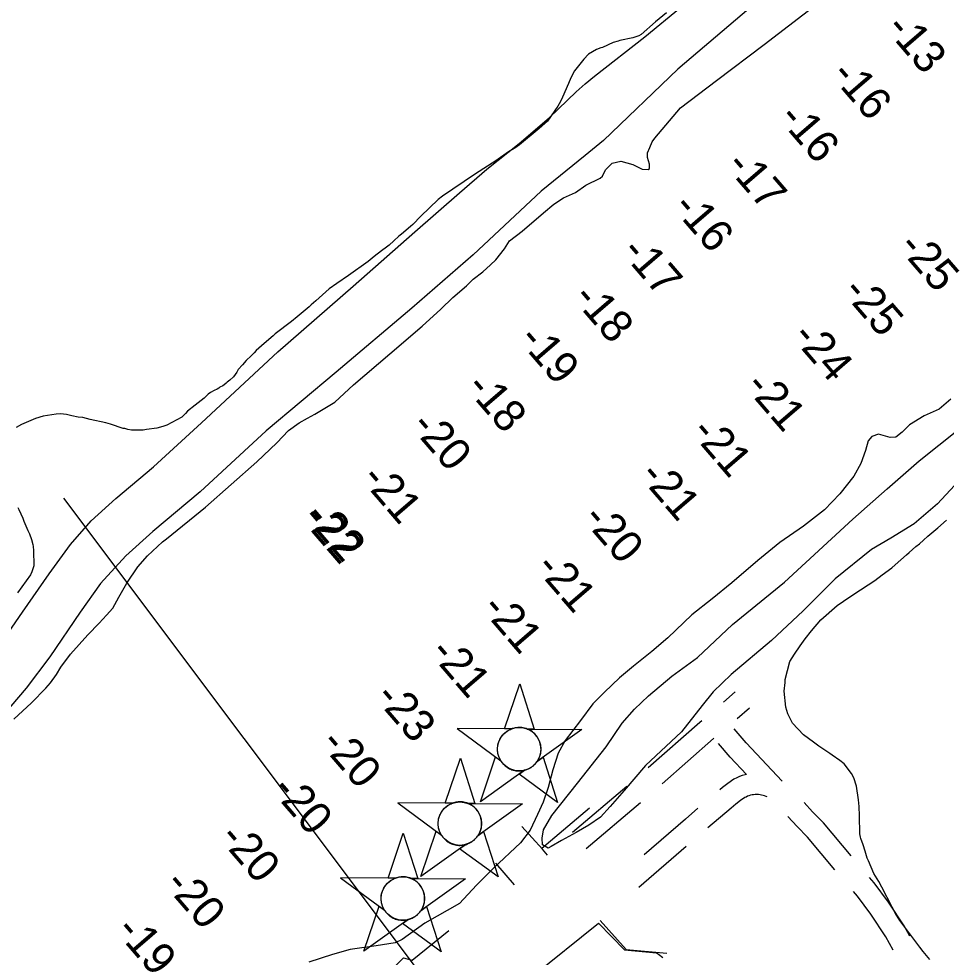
# Model space of a CAD drawing. Extents: x 3704301 to 3742427, y 506229 to 532009.
# Drawn here: x 3709544 to 3710847, y 515118 to 516437 of the extents above; entities that cross this region are included whole.
import ezdxf

# ---------------------------------------------------------------- set-up
doc = ezdxf.new("R2010")
doc.units = 0
for name, color, linetype in [('V-CHAN-NAID', 7, 'Continuous'), ('V-FLOD-BASE', 7, 'Continuous'), ('V-LEVE-TOET', 7, 'Continuous'), ('V-ROAD-CNTR', 7, 'Continuous'), ('V-RRAP-FSHR', 7, 'Continuous'), ('V-SITE-VEGE', 7, 'Continuous'), ('V-TOPO-SHOR', 7, 'Continuous'), ('V-TOPO-SPOT', 7, 'Continuous'), ('V-UTIL-LINE', 7, 'Continuous')]:
    doc.layers.add(name, color=color, linetype=linetype)

msp = doc.modelspace()

# ---------------------------------------------------------------- linework, layer by layer
at = {"layer": 'V-CHAN-NAID'}
for points in [[(3710236.4, 515438.8), (3710226.8, 515438.9), (3710248, 515502.3), (3710268.2, 515438.6), (3710258.6, 515438.6), (3710257, 515439.2), (3710254.9, 515439.8), (3710252.9, 515440.3), (3710250.9, 515440.6), (3710249.7, 515440.7), (3710248.2, 515440.8), (3710246.4, 515440.8), (3710245.1, 515440.7), (3710243.2, 515440.5), (3710241.8, 515440.3), (3710240, 515439.9), (3710238.5, 515439.5), (3710237.4, 515439.2)], [(3710236.4, 515438.8), (3710159.9, 515439.3), (3710221.5, 515393.9), (3710220.4, 515395.8), (3710219.6, 515397.5), (3710218.8, 515399.4), (3710218.1, 515401.5), (3710217.7, 515402.8), (3710217.3, 515404.4), (3710217.1, 515405.9), (3710216.9, 515407.5), (3710216.8, 515409.2), (3710216.8, 515410.8), (3710216.9, 515412.9), (3710217.1, 515414.5), (3710217.5, 515416.7), (3710217.9, 515418.6), (3710218.5, 515420.5), (3710219.2, 515422.2), (3710219.9, 515423.8), (3710220.7, 515425.3), (3710221.8, 515427.1), (3710222.8, 515428.5), (3710223.8, 515429.8), (3710224.8, 515430.9), (3710226.1, 515432.3), (3710227.2, 515433.2), (3710228.9, 515434.6), (3710230.1, 515435.5), (3710231.8, 515436.6), (3710233.5, 515437.5), (3710235, 515438.2)], [(3710258.6, 515438.6), (3710335.1, 515438.1), (3710272.9, 515393.6), (3710273.8, 515395.1), (3710274.8, 515396.9), (3710275.5, 515398.5), (3710276.2, 515400.5), (3710276.8, 515402.2), (3710277.2, 515403.9), (3710277.5, 515405.9), (3710277.7, 515407.5), (3710277.9, 515409.7), (3710277.8, 515411.7), (3710277.6, 515413.9), (3710277.4, 515415.7), (3710276.9, 515417.9), (3710276.2, 515420.1), (3710275.5, 515422.1), (3710274.8, 515423.5), (3710273.8, 515425.4), (3710272.8, 515427.1), (3710271.6, 515428.8), (3710270.3, 515430.4), (3710269, 515431.7), (3710267.4, 515433.3), (3710265.7, 515434.7), (3710264, 515435.9), (3710262.1, 515437), (3710260.6, 515437.8)], [(3710153, 515334.3), (3710143.4, 515334.3), (3710164.6, 515397.8), (3710184.8, 515334), (3710175.2, 515334.1), (3710173.6, 515334.7), (3710171.5, 515335.3), (3710169.5, 515335.7), (3710167.4, 515336.1), (3710166.3, 515336.2), (3710164.7, 515336.2), (3710163, 515336.2), (3710161.6, 515336.2), (3710159.7, 515336), (3710158.4, 515335.8), (3710156.6, 515335.4), (3710155.1, 515335), (3710154, 515334.6)], [(3710254.9, 515380.7), (3710192.7, 515336.1), (3710213.8, 515399.6), (3710221.5, 515393.9), (3710222.1, 515393), (3710223.5, 515391.1), (3710224.7, 515389.7), (3710226.2, 515388.2), (3710227.6, 515386.9), (3710229, 515385.8), (3710230.4, 515384.8), (3710232.1, 515383.8), (3710233.8, 515382.9), (3710235.6, 515382), (3710237.1, 515381.5), (3710238.7, 515381), (3710240.9, 515380.4), (3710242.5, 515380.1), (3710244.5, 515379.9), (3710246, 515379.7), (3710247.9, 515379.7), (3710249.6, 515379.8), (3710251.3, 515380), (3710253.2, 515380.3)], [(3710272.9, 515393.6), (3710280.7, 515399.2), (3710300.9, 515335.4), (3710247.1, 515375.1), (3710254.9, 515380.7), (3710256.5, 515381.1), (3710258.1, 515381.7), (3710260.3, 515382.6), (3710262, 515383.5), (3710263.9, 515384.6), (3710265.6, 515385.8), (3710267.2, 515387.1), (3710268.5, 515388.2), (3710269.9, 515389.7), (3710271.1, 515391.1), (3710272.2, 515392.5)], [(3710153, 515334.3), (3710076.5, 515334.8), (3710138.1, 515289.4), (3710137, 515291.3), (3710136.2, 515292.9), (3710135.3, 515294.9), (3710134.6, 515297), (3710134.3, 515298.3), (3710133.9, 515299.9), (3710133.7, 515301.3), (3710133.5, 515302.9), (3710133.4, 515304.7), (3710133.4, 515306.3), (3710133.5, 515308.3), (3710133.7, 515310), (3710134, 515312.2), (3710134.5, 515314.1), (3710135.1, 515316), (3710135.8, 515317.6), (3710136.5, 515319.2), (3710137.3, 515320.8), (3710138.4, 515322.5), (3710139.4, 515324), (3710140.4, 515325.2), (3710141.4, 515326.4), (3710142.7, 515327.7), (3710143.8, 515328.7), (3710145.5, 515330.1), (3710146.7, 515331), (3710148.4, 515332), (3710150.1, 515333), (3710151.6, 515333.7)], [(3710175.2, 515334.1), (3710251.7, 515333.6), (3710189.5, 515289), (3710190.4, 515290.5), (3710191.4, 515292.4), (3710192.1, 515294), (3710192.8, 515295.9), (3710193.4, 515297.7), (3710193.8, 515299.3), (3710194.1, 515301.3), (3710194.3, 515302.9), (3710194.4, 515305.1), (3710194.4, 515307.2), (3710194.2, 515309.4), (3710193.9, 515311.2), (3710193.5, 515313.4), (3710192.8, 515315.5), (3710192.1, 515317.5), (3710191.4, 515319), (3710190.4, 515320.9), (3710189.4, 515322.6), (3710188.1, 515324.3), (3710186.9, 515325.8), (3710185.6, 515327.2), (3710184, 515328.7), (3710182.2, 515330.1), (3710180.5, 515331.3), (3710178.7, 515332.5), (3710177.2, 515333.2)], [(3710072.9, 515229), (3710063.3, 515229), (3710084.4, 515292.5), (3710104.7, 515228.7), (3710095.1, 515228.8), (3710093.5, 515229.4), (3710091.4, 515230), (3710089.4, 515230.4), (3710087.3, 515230.8), (3710086.2, 515230.9), (3710084.6, 515230.9), (3710082.9, 515230.9), (3710081.5, 515230.9), (3710079.6, 515230.7), (3710078.3, 515230.5), (3710076.5, 515230.1), (3710075, 515229.7), (3710073.9, 515229.3)], [(3710171.4, 515276.1), (3710109.2, 515231.6), (3710130.4, 515295.1), (3710138.1, 515289.4), (3710138.7, 515288.4), (3710140.1, 515286.6), (3710141.3, 515285.2), (3710142.8, 515283.7), (3710144.2, 515282.4), (3710145.6, 515281.2), (3710147, 515280.3), (3710148.7, 515279.2), (3710150.4, 515278.3), (3710152.2, 515277.5), (3710153.7, 515276.9), (3710155.3, 515276.4), (3710157.5, 515275.9), (3710159, 515275.6), (3710161.1, 515275.3), (3710162.6, 515275.2), (3710164.5, 515275.2), (3710166.2, 515275.3), (3710167.9, 515275.4), (3710169.8, 515275.7)], [(3710189.5, 515289), (3710197.3, 515294.6), (3710217.5, 515230.8), (3710163.6, 515270.5), (3710171.4, 515276.1), (3710173.1, 515276.6), (3710174.7, 515277.2), (3710176.9, 515278.1), (3710178.6, 515279), (3710180.5, 515280.1), (3710182.2, 515281.3), (3710183.8, 515282.5), (3710185.1, 515283.7), (3710186.4, 515285.1), (3710187.6, 515286.5), (3710188.8, 515288)], [(3710072.9, 515229), (3709996.4, 515229.5), (3710058, 515184.1), (3710056.9, 515186), (3710056.1, 515187.6), (3710055.2, 515189.6), (3710054.5, 515191.7), (3710054.2, 515193), (3710053.8, 515194.6), (3710053.6, 515196.1), (3710053.4, 515197.6), (3710053.3, 515199.4), (3710053.3, 515201), (3710053.4, 515203), (3710053.5, 515204.7), (3710053.9, 515206.9), (3710054.4, 515208.8), (3710055, 515210.7), (3710055.7, 515212.3), (3710056.4, 515213.9), (3710057.2, 515215.5), (3710058.3, 515217.2), (3710059.3, 515218.7), (3710060.3, 515219.9), (3710061.3, 515221.1), (3710062.6, 515222.4), (3710063.7, 515223.4), (3710065.4, 515224.8), (3710066.6, 515225.7), (3710068.3, 515226.7), (3710070, 515227.7), (3710071.5, 515228.4)], [(3710095.1, 515228.8), (3710171.6, 515228.3), (3710109.4, 515183.7), (3710110.3, 515185.2), (3710111.3, 515187.1), (3710112, 515188.7), (3710112.7, 515190.6), (3710113.3, 515192.4), (3710113.7, 515194), (3710114, 515196), (3710114.2, 515197.6), (3710114.3, 515199.8), (3710114.3, 515201.9), (3710114.1, 515204.1), (3710113.8, 515205.9), (3710113.4, 515208.1), (3710112.7, 515210.2), (3710112, 515212.2), (3710111.3, 515213.7), (3710110.3, 515215.6), (3710109.2, 515217.3), (3710108, 515219), (3710106.8, 515220.5), (3710105.5, 515221.9), (3710103.9, 515223.4), (3710102.1, 515224.8), (3710100.4, 515226), (3710098.6, 515227.2), (3710097.1, 515227.9)], [(3710091.3, 515170.8), (3710029.1, 515126.3), (3710050.3, 515189.8), (3710058, 515184.1), (3710058.6, 515183.1), (3710060, 515181.3), (3710061.2, 515179.9), (3710062.7, 515178.4), (3710064.1, 515177.1), (3710065.5, 515175.9), (3710066.9, 515175), (3710068.6, 515173.9), (3710070.3, 515173), (3710072.1, 515172.2), (3710073.6, 515171.6), (3710075.2, 515171.1), (3710077.4, 515170.6), (3710078.9, 515170.3), (3710081, 515170), (3710082.5, 515169.9), (3710084.4, 515169.9), (3710086.1, 515170), (3710087.8, 515170.1), (3710089.7, 515170.4)], [(3710109.4, 515183.7), (3710117.2, 515189.3), (3710137.4, 515125.5), (3710083.5, 515165.2), (3710091.3, 515170.8), (3710093, 515171.3), (3710094.6, 515171.9), (3710096.8, 515172.8), (3710098.5, 515173.7), (3710100.4, 515174.8), (3710102.1, 515176), (3710103.7, 515177.2), (3710105, 515178.4), (3710106.3, 515179.8), (3710107.5, 515181.2), (3710108.7, 515182.7)]]:
    msp.add_lwpolyline(points, close=True, dxfattribs=at)
for centre in [(3710247.3, 515410.3), (3710163.9, 515305.7), (3710083.8, 515200.4)]:
    msp.add_circle(centre, 30.5, dxfattribs=at)
at = {"layer": 'V-FLOD-BASE'}
for p, q in [((3710346, 515327.6), (3710279.1, 515270.7)), ((3710240.8, 515219.7), (3710214.2, 515250.2))]:
    msp.add_line(p, q, dxfattribs=at)
for points in [[(3710287, 515261.3), (3710279.8, 515269.9), (3710250.9, 515301.8)], [(3710059.4, 515092), (3710084.7, 515116.9), (3710096.7, 515113.8), (3710148.5, 515155.7)]]:
    msp.add_lwpolyline(points, dxfattribs=at)
at = {"layer": 'V-LEVE-TOET'}
msp.add_line((3710504.2, 515471.6), (3710475.1, 515434.5), dxfattribs=at)
for points in [[(3710632.1, 516504.1), (3710470.3, 516365.7), (3710365.7, 516265.6), (3710339.9, 516244.3), (3710278.3, 516194.5), (3710182.8, 516104.9), (3710096.2, 516030), (3709990, 515940.2), (3709891.9, 515857.7), (3709798.9, 515771.8), (3709732.5, 515716), (3709694.6, 515681.9), (3709659, 515643.1), (3709630.3, 515602.7), (3709588, 515540.2), (3709554.5, 515496.2), (3709502.9, 515436.3)], [(3709519.4, 515559.1), (3709549.5, 515602.7), (3709587, 515656.9), (3709617, 515697.7), (3709646, 515731.1), (3709680.5, 515762.5), (3709733.6, 515806.9), (3709800.7, 515868.7), (3709908.1, 515968.8), (3710013.9, 516060.9), (3710100.5, 516137.2), (3710163.2, 516192.1), (3710202, 516225.2), (3710247.4, 516261.4), (3710290, 516297.7), (3710327.4, 516334.1), (3710339.9, 516345), (3710353.2, 516355.9), (3710423.9, 516411.5), (3710523.8, 516494)], [(3711639.9, 516469.9), (3711568, 516405.4), (3711481.5, 516332.4), (3711377.6, 516243.9), (3711287.2, 516165.9), (3711160.2, 516051.4), (3711038.6, 515943.8), (3710962.4, 515875.2), (3710904, 515825.3), (3710877.2, 515800.3), (3710834.8, 515755.1), (3710802.3, 515727), (3710769.5, 515706.8), (3710742.4, 515690.7), (3710691.3, 515649.9), (3710646.1, 515604.8), (3710601.5, 515563), (3710545.1, 515515.4), (3710519.7, 515490.8), (3710504.2, 515471.6)], [(3710475.1, 515434.5), (3710424.8, 515387.2), (3710394.9, 515352.4), (3710375.1, 515330), (3710361.6, 515314.9), (3710344.9, 515303.7), (3710327.4, 515293.4), (3710306.9, 515281.8), (3710292.2, 515273.7), (3710288, 515271.1), (3710280.1, 515275.9), (3710279.4, 515285.3), (3710281.6, 515296.9), (3710292.9, 515317.2), (3710329.2, 515362.6), (3710369.4, 515413.4), (3710391.8, 515447), (3710409.1, 515466.6), (3710428.8, 515485.3), (3710461.8, 515512.9), (3710497.6, 515539.1), (3710546.9, 515585.5), (3710620.1, 515644.8), (3710715.9, 515733.5), (3710764.3, 515776.1), (3710809.3, 515815.6), (3710864.3, 515859.6)]]:
    msp.add_lwpolyline(points, dxfattribs=at)
at = {"layer": 'V-ROAD-CNTR'}
for p, q in [((3710534.2, 515476.4), (3710550.8, 515491)), ((3710553.5, 515453.5), (3710570.6, 515468.4)), ((3710322, 515293.8), (3710398.5, 515358.2)), ((3710341.3, 515270.9), (3710417.8, 515335.3)), ((3710482, 515273.5), (3710415.1, 515216))]:
    msp.add_line(p, q, dxfattribs=at)
for points in [[(3710428.6, 515384.6), (3710500.9, 515448.2), (3710503.8, 515450.5)], [(3710616.7, 515365.2), (3710566, 515419.3), (3710549.3, 515439)], [(3710447.9, 515361.6), (3710520.3, 515425.3), (3710520.9, 515425.8)], [(3710566.4, 515374.9), (3710543.6, 515399.3), (3710527.4, 515418.5)], [(3710566.4, 515374.9), (3710564.6, 515374.5), (3710560.6, 515373.3), (3710556.6, 515371.9), (3710552.8, 515370.2), (3710548.6, 515368), (3710540.4, 515362.1), (3710533, 515356.5), (3710528.9, 515353.1)], [(3710595.8, 515343.2), (3710594.2, 515343.9), (3710592.1, 515344.7), (3710590, 515345.4), (3710587.8, 515345.9), (3710585.6, 515346.3), (3710583.3, 515346.5), (3710581.1, 515346.6), (3710578.8, 515346.5), (3710576.6, 515346.3), (3710574.4, 515346), (3710572.2, 515345.5), (3710570, 515344.8), (3710567.9, 515344.1), (3710565.9, 515343.1), (3710564.4, 515342.4), (3710558.2, 515338), (3710551.5, 515332.9), (3710545, 515327.6), (3710512.3, 515299.6)], [(3710498.4, 515327.2), (3710480.8, 515312.1), (3710422.6, 515262)], [(3710713.8, 515260.3), (3710674.6, 515306.6), (3710659.3, 515322.5), (3710647.5, 515335.2)], [(3710690.8, 515241), (3710652.3, 515286.5), (3710637.6, 515301.9), (3710624.5, 515315.8)], [(3710796.1, 515147.5), (3710788, 515162), (3710766.1, 515195.5), (3710745.8, 515222.4), (3710739.6, 515229.8)], [(3710772.6, 515127.8), (3710762.3, 515146.5), (3710741.5, 515178.3), (3710722.4, 515203.7), (3710716.7, 515210.5)]]:
    msp.add_lwpolyline(points, dxfattribs=at)
at = {"layer": 'V-RRAP-FSHR'}
msp.add_lwpolyline([(3710361.2, 515169.8), (3710397.3, 515128.7), (3710454.6, 515123.5)], dxfattribs=at)
at = {"layer": 'V-SITE-VEGE'}
for points in [[(3710454.2, 516444.9), (3710438.8, 516432.2), (3710418.7, 516414.7), (3710415.2, 516412.8), (3710407, 516410), (3710388.8, 516405.9), (3710386.3, 516405), (3710379.2, 516403.2), (3710364.4, 516396.5), (3710361.9, 516395.6), (3710355.8, 516393.7), (3710344.6, 516387), (3710337.9, 516380.1), (3710324.8, 516363.4), (3710319.6, 516353.5), (3710316.3, 516345.5), (3710308.3, 516326.6), (3710305.1, 516320.2), (3710301.4, 516313.7), (3710286.8, 516293), (3710275.4, 516282.3), (3710247.7, 516259.4), (3710242.5, 516256), (3710232.3, 516249.7), (3710214.4, 516237.1), (3710185.7, 516218.8), (3710154, 516197), (3710139.6, 516187.3), (3710133.5, 516182.5), (3710109.2, 516159.5), (3710097.9, 516147.7), (3710094.3, 516144.8), (3710081.9, 516134.1), (3710078.3, 516131.2), (3710071.1, 516124.8), (3710064.4, 516118.5), (3710060.8, 516115.5), (3710053.6, 516110.7), (3710043.4, 516102.4), (3710035.1, 516095.6), (3710007.5, 516075.7), (3709991.1, 516064.6), (3709980.3, 516057.4), (3709961.3, 516040.3), (3709955.1, 516034.9), (3709952, 516032), (3709935.5, 516017.8), (3709927.3, 516011.5), (3709904.2, 515994), (3709901.6, 515991.1), (3709888.8, 515980.4), (3709877.9, 515970.6), (3709874.8, 515967.2), (3709870.7, 515963.2), (3709863.5, 515956.4), (3709858.3, 515950.5), (3709852.6, 515943.6), (3709850.5, 515940.2), (3709845.8, 515933.7), (3709840.6, 515928.9), (3709837, 515925.9), (3709835.5, 515924.5), (3709832.9, 515922.5), (3709830.9, 515921.1), (3709826.8, 515919.2), (3709825.2, 515917.7), (3709822.7, 515916.3), (3709818.6, 515914.4), (3709813.5, 515911.5)], [(3709813.5, 515911.5), (3709810.4, 515909), (3709805.3, 515904), (3709804.7, 515903.5), (3709792.2, 515893.8), (3709781.4, 515885.1), (3709778.6, 515882), (3709773.1, 515876.8), (3709752.1, 515865.8), (3709746.7, 515863.8), (3709738.2, 515861.4), (3709723.8, 515859.7), (3709719, 515858.8), (3709714.7, 515858.4), (3709702.5, 515858.8), (3709697.2, 515859.5), (3709693, 515860.7), (3709690.9, 515860.7), (3709673.1, 515867.1), (3709666.7, 515868.9), (3709644.6, 515873.8), (3709634, 515876.2), (3709627.7, 515876.9), (3709618.7, 515878.8), (3709611.3, 515880.6), (3709602.9, 515881.4), (3709596.5, 515881), (3709578.4, 515878.4), (3709567.6, 515875), (3709547.8, 515866.6), (3709540.7, 515862.5)], [(3709542.7, 515749.9), (3709544.2, 515747.2), (3709549.7, 515734.9), (3709551.1, 515730.6), (3709557.1, 515717.7), (3709559.1, 515712.8), (3709562, 515704.8), (3709564, 515697.8), (3709564.4, 515695.1), (3709564.8, 515689.3), (3709565.2, 515668), (3709562.3, 515659.6), (3709560.6, 515655.4), (3709542.3, 515630)], [(3710627.6, 515533.4), (3710633.9, 515543.8), (3710641.8, 515555.7), (3710649.1, 515565.5), (3710657.9, 515576.8), (3710670.9, 515592.1), (3710694.1, 515612.1), (3710702.8, 515618.4), (3710717.6, 515628), (3710746.8, 515647.4), (3710757.1, 515655.1), (3710770.9, 515665.3), (3710775.5, 515669.2), (3710791.5, 515683.4), (3710795.1, 515686.8), (3710804.4, 515695.1), (3710809.5, 515699), (3710815.2, 515703.9), (3710821.4, 515709.7), (3710835.3, 515721.4), (3710847.6, 515732.2)], [(3710824.1, 515114.9), (3710814.8, 515126.2), (3710810, 515131.9), (3710781.8, 515169.8), (3710776, 515179.5), (3710771.2, 515188.2), (3710756.9, 515216.2), (3710752.6, 515224.4), (3710745.4, 515235.6), (3710737.8, 515253.4), (3710735.9, 515257), (3710733.1, 515267.1), (3710730.3, 515275.8), (3710727.1, 515284.9), (3710726.6, 515286.9), (3710726.2, 515288.9), (3710725.7, 515291.5), (3710725.4, 515316.6), (3710724.7, 515329.7), (3710724, 515339.3), (3710721, 515358.5), (3710717.3, 515370.1), (3710713.9, 515376.3), (3710703.7, 515389.6), (3710697.8, 515394.3), (3710687, 515402.1), (3710683.5, 515404.2), (3710668.2, 515414.7), (3710660.8, 515420.4), (3710653.9, 515425.1), (3710646.5, 515430.3), (3710631.3, 515446.8), (3710624.7, 515460.1), (3710621.9, 515469.2), (3710619.5, 515491.9), (3710620.8, 515503.9), (3710620.9, 515508), (3710627.6, 515533.4)]]:
    msp.add_lwpolyline(points, dxfattribs=at)
at = {"layer": 'V-TOPO-SHOR'}
for points in [[(3710214.6, 516097.8), (3710226.7, 516113.5), (3710233.6, 516124.7), (3710251.5, 516138), (3710281.3, 516163.9), (3710295.8, 516176), (3710309.7, 516185.1), (3710326.5, 516192.4), (3710341, 516202.7), (3710360.8, 516212.8), (3710364.1, 516215.7), (3710368.5, 516224.5), (3710377.7, 516233.7), (3710390.2, 516236.4), (3710406.7, 516231.8), (3710420.1, 516225.5), (3710428.4, 516224.7), (3710430.2, 516226.4), (3710430.5, 516232.3), (3710427.3, 516241.9), (3710427.4, 516248.4), (3710430.8, 516255.6), (3710434, 516263.5), (3710438, 516269), (3710474, 516311.4), (3710524.3, 516349.7), (3710591.5, 516400.7), (3710679.9, 516468.9)], [(3709537.1, 515452.4), (3709562.2, 515475.5), (3709582.4, 515496), (3709588.6, 515503.6), (3709597.2, 515515.2), (3709603.4, 515525.7), (3709616.9, 515543.8), (3709641.3, 515571), (3709657.2, 515587.2), (3709667.6, 515598.8), (3709676.1, 515608.6), (3709684.9, 515623.8), (3709696.1, 515643.7), (3709711.5, 515666.4), (3709725, 515682.1), (3709746.2, 515701.7), (3709751.6, 515706.1), (3709806.5, 515750.4), (3709878.8, 515814.3), (3709906.7, 515840.9), (3709923.2, 515858.2), (3709938.3, 515869.1), (3709949.8, 515875.3), (3709960, 515881), (3709988.3, 515898), (3710014.5, 515922.2), (3710065.5, 515966), (3710111, 516004.5), (3710137.1, 516028.7), (3710154.1, 516044.9), (3710173, 516061.6), (3710182.7, 516070.8), (3710196.1, 516081.1), (3710206.7, 516090.9), (3710214.6, 516097.8)], [(3710853.6, 515902), (3710837.2, 515888.2), (3710816.2, 515878.7), (3710795.7, 515866.2), (3710785.3, 515855.8), (3710776.3, 515848.9), (3710768.5, 515848.5), (3710758.5, 515851.2), (3710752.1, 515853.1), (3710742.5, 515849.8), (3710737.6, 515843.4), (3710733.6, 515829.9), (3710727.2, 515811.7), (3710717.3, 515794.1), (3710697.6, 515769.2), (3710676.3, 515746.6), (3710646.6, 515723.6), (3710613.4, 515700.8), (3710582.5, 515675.5), (3710546, 515643.9), (3710518.2, 515621.5), (3710489.7, 515599.1), (3710456.2, 515566.8), (3710433.8, 515547.8), (3710407.7, 515527.1), (3710388.3, 515510.4), (3710367, 515490.2), (3710350.5, 515474.1), (3710333.3, 515450.8), (3710311.8, 515422.3), (3710301.9, 515404.8), (3710294.7, 515381.2), (3710288.1, 515356.5), (3710281.1, 515335.9), (3710272.9, 515318.3), (3710262.8, 515296.7), (3710249.3, 515278.6), (3710211, 515242.9), (3710187.2, 515219.2), (3710163.4, 515193.7), (3710114.6, 515165.9), (3710082.6, 515143.1), (3710073, 515138), (3710046.2, 515133.9), (3710009.8, 515129), (3709984.8, 515121.9), (3709951.8, 515110.9)], [(3710265.5, 515091.1), (3710358.5, 515166), (3710395.4, 515128.3), (3710440.2, 515124.1), (3710443.1, 515122.4), (3710448.9, 515117.5)]]:
    msp.add_lwpolyline(points, dxfattribs=at)
at = {"layer": 'V-UTIL-LINE'}
msp.add_line((3710245.5, 514912.6), (3709607.5, 515762.9), dxfattribs=at)

# ---------------------------------------------------------------- texts
at = {"layer": 'V-TOPO-SPOT'}
for s, p in [('-13', (3710760.3, 516422.3)), ('-16', (3710683.5, 516356.9)), ('-16', (3710609.9, 516296.5)), ('-17', (3710535.7, 516229.7)), ('-16', (3710461.2, 516171.1)), ('-17', (3710388.9, 516108.6)), ('-25', (3710778, 516115.5)), ('-18', (3710320.9, 516043.7)), ('-25', (3710699.8, 516052.8)), ('-24', (3710628.9, 515989.2)), ('-19', (3710244.5, 515985.3)), ('-18', (3710170.5, 515917.8)), ('-21', (3710562.8, 515919.5)), ('-20', (3710093.2, 515863.7)), ('-21', (3710487, 515855.2)), ('-21', (3710414.4, 515794.1)), ('-21', (3710023.4, 515789.7)), ('-22', (3709939.8, 515733.6)), ('-22', (3709944.1, 515736.5)), ('-20', (3710334.7, 515733.7)), ('-21', (3710268.2, 515665)), ('-21', (3710192.7, 515607.4)), ('-21', (3710119.8, 515545.3)), ('-23', (3710042.8, 515482.6)), ('-20', (3709966.3, 515417.8)), ('-20', (3709897.8, 515352.4)), ('-20', (3709824.1, 515285)), ('-20', (3709747.3, 515220)), ('-19', (3709678.5, 515154.7))]:
    msp.add_text(s, height=45, rotation=310.7207, dxfattribs=at).set_placement(p)

doc.saveas('drawing.dxf')
